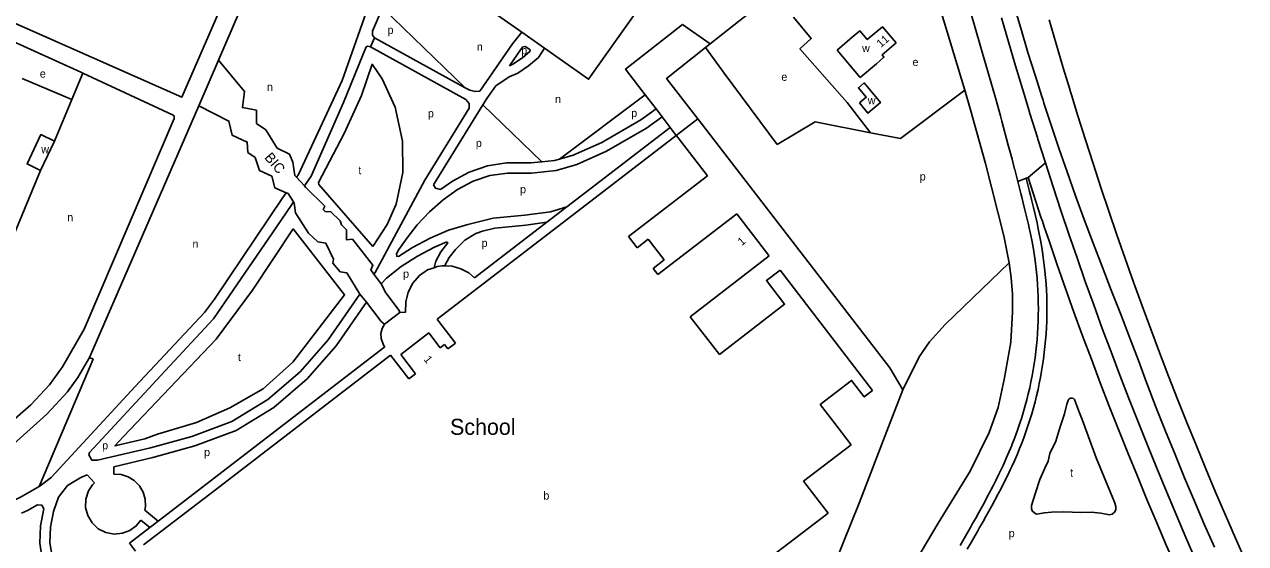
# Model space of a CAD drawing. Extents: x 155317 to 156514, y 385353 to 386894.
# Drawn here: x 155844 to 156455, y 385769 to 386029 of the extents above; entities that cross this region are included whole.
import ezdxf

# ---------------------------------------------------------------- set-up
doc = ezdxf.new("R2010")
doc.units = 0
for name, color, linetype in [('BLT_Basislijn', 7, 'Continuous'), ('BLT_Bebouwing', 7, 'Continuous'), ('BLT_Bebouwing_beschrifting', 7, 'Continuous'), ('BLT_Centroide', 7, 'Continuous'), ('BLT_Huisnummer', 7, 'Continuous'), ('BLT_Huisnummer_reeks', 7, 'Continuous'), ('BLT_Straatnaam', 7, 'Continuous'), ('BLT_Vlakafsluiter', 7, 'Continuous')]:
    doc.layers.add(name, color=color, linetype=linetype)

msp = doc.modelspace()

# ---------------------------------------------------------------- linework, layer by layer
at = {"layer": 'BLT_Basislijn'}
for p, q in [((155973.89, 386086.05), (155941.31, 386010.86)), ((156018.39, 386025.39), (156023.37, 386037.09)), ((156023.37, 386037.09), (156064.66, 385997.16)), ((156173.26, 386028.79), (156187.01, 386019.05)), ((156003.79, 385989.7), (156015.08, 386017.51)), ((156017.27, 386017.58), (156064.88, 385991.33)), ((156019.37, 386022.13), (156064.66, 385997.16)), ((156187.01, 386019.05), (156184.67, 386017.19)), ((156194.08, 386004.44), (156184.67, 386017.19)), ((155941.31, 386010.86), (155931.48, 385988.18)), ((155873.59, 386004.4), (155868.11, 385991.31)), ((156220.55, 385968.74), (156194.08, 386004.44)), ((155843.34, 386001.85), (155868.11, 385991.31)), ((156064.66, 385997.16), (156066.95, 385995.9)), ((156111.68, 385961.46), (156154.54, 385993.63)), ((156154.54, 385993.63), (156159.99, 385986.54)), ((156282.13, 385971.86), (156314.22, 385995.98)), ((155868.11, 385991.31), (155859.4, 385970.5)), ((155931.48, 385988.18), (155876.96, 385862.37)), ((156073.5, 385988.61), (156048.76, 385948.55)), ((156073.5, 385988.61), (156102.99, 385960.1)), ((156159.99, 385986.54), (156163.04, 385982.57)), ((156255.52, 385989.78), (156267.23, 385974.68)), ((156163.04, 385982.57), (156167.08, 385977.32)), ((156180.81, 385981.6), (156170.13, 385973.36)), ((156239.46, 385980.12), (156220.55, 385968.74)), ((156267.23, 385974.68), (156239.46, 385980.12)), ((156167.08, 385977.32), (156115.43, 385937.61)), ((156167.08, 385977.32), (156170.13, 385973.36)), ((156267.23, 385974.68), (156282.13, 385971.86)), ((155984.34, 385948.05), (155980.42, 385952.4)), ((155973.58, 385942.24), (155975.22, 385944.67)), ((155978.84, 385940.06), (155977.67, 385938.36)), ((156115.43, 385937.61), (156105.41, 385929.9)), ((156105.41, 385929.9), (156069.26, 385902.1)), ((156031.43, 385916.29), (156030.27, 385914.14)), ((156022.58, 385899.2), (156018.95, 385903.92)), ((156012.02, 385893.97), (156015.31, 385889.95)), ((156031.93, 385884.79), (156024.38, 385879.01)), ((156024.41, 385867.64), (155911.16, 385780.55)), ((155914.68, 385855.74), (155876.89, 385814.79)), ((155861.89, 385840.81), (155855.6, 385834)), ((155855.6, 385834), (155824.79, 385806.32)), ((155879.36, 385799.78), (155875.78, 385803.77)), ((155889.02, 385807.76), (155889.07, 385804.08)), ((155904.52, 385785.98), (155911.16, 385780.55)), ((155902.59, 385781.1), (155907.09, 385777.42)), ((155911.16, 385780.55), (155907.09, 385777.42)), ((155907.09, 385777.42), (155896.92, 385769.6)), ((155896.92, 385769.6), (155899.98, 385765.62))]:
    msp.add_line(p, q, dxfattribs=at)
for points in [[(156004.97, 386182.89), (155998.89, 386166.67), (155923.01, 385992.36), (155820.9, 386037.51)], [(156314.22, 385995.98), (156304.95, 386026.73), (156294.45, 386061.41)], [(156215.7, 386041.67), (156202.11, 386030.96), (156187.01, 386019.05)], [(155980.42, 385952.4), (155981.11, 385953.42), (156003.09, 386000.75), (156017.22, 386040.43)], [(156315.56, 386040.22), (156319.05, 386028.17), (156322.58, 386016.14), (156326.11, 386004.1), (156329.55, 385992.04), (156332.06, 385983.05), (156332.76, 385980.47)], [(156338.97, 386037.95), (156342.22, 386026.86), (156345.83, 386014.84), (156349.54, 386002.85), (156352.74, 385992.79), (156352.76, 385992.71), (156353.35, 385990.88), (156353.8, 385989.51), (156357.28, 385978.91), (156361.31, 385966.96), (156365.44, 385955.05), (156369.66, 385943.17), (156373.99, 385931.33), (156378.41, 385919.53), (156382.93, 385907.77), (156387.48, 385896.02), (156392.03, 385884.28), (156396.58, 385872.54), (156401.12, 385860.8), (156404.98, 385849.88), (156405.34, 385848.94), (156409.93, 385837.21), (156414.59, 385825.52), (156419.32, 385813.85), (156424.12, 385802.21), (156429, 385790.61), (156433.95, 385779.03), (156438.97, 385767.49)], [(156173.26, 386028.79), (156144.77, 386006.45), (156154.54, 385993.63)], [(156255.52, 385989.78), (156231.88, 386016.58), (156237.51, 386021.7), (156228.62, 386032.5)], [(156332.54, 386032.1), (156336.06, 386020.11), (156339.61, 386008.13), (156343.2, 385996.16), (156345.9, 385987.26), (156346.83, 385984.2), (156350.53, 385972.26), (156350.77, 385971.48), (156354.54, 385959.56)], [(156454.56, 385760.66), (156449.5, 385772.11), (156444.51, 385783.59), (156439.59, 385795.1), (156434.74, 385806.64), (156429.96, 385818.21), (156425.26, 385829.81), (156420.63, 385841.44), (156416.07, 385853.09), (156411.58, 385864.78), (156407.17, 385876.49), (156402.83, 385888.23), (156398.57, 385900), (156394.37, 385911.8), (156390.25, 385923.62), (156386.21, 385935.46), (156382.24, 385947.34), (156378.34, 385959.23), (156374.52, 385971.15), (156370.78, 385983.09), (156367.52, 385993.68), (156367.1, 385995.06), (156366.55, 385996.89), (156366.53, 385996.97), (156363.49, 386007.03), (156359.91, 386019.02), (156356.36, 386031.02)], [(156018.39, 386025.39), (156018.39, 386023.48), (156019.37, 386022.13)], [(156092.94, 386024.92), (156088.32, 386019.14), (156071.88, 385995.4), (156069.55, 385995.19), (156066.95, 385995.9)], [(155835.04, 386021.99), (155872.5, 386004.9), (155873.59, 386004.4)], [(156015.08, 386017.51), (156016.06, 386017.87), (156017.27, 386017.58)], [(156079.87, 385998.15), (156086.66, 386002.62), (156090.92, 386004.44), (156096.24, 386008.07), (156101.21, 386012.32), (156104.28, 386016.92)], [(156086.76, 386008.1), (156088.51, 386008.85), (156093.2, 386012.04), (156097.16, 386015.44), (156096.94, 386016.34), (156094.62, 386017.8), (156093.47, 386017.58)], [(156093.47, 386017.58), (156092.33, 386016.15), (156086.76, 386008.1)], [(156180.81, 385981.6), (156165.29, 386001.85), (156184.67, 386017.19)], [(155980.42, 385952.4), (155979.58, 385953.33), (155978.47, 385960.03), (155976.88, 385963.96), (155970.69, 385967), (155965.05, 385976.04), (155960.31, 385979.29), (155960.31, 385985.94), (155953.35, 385987.2), (155954.43, 385995.3), (155941.31, 386010.86)], [(155873.59, 386004.4), (155918.45, 385983.68), (155919.24, 385983.05), (155919.21, 385981.83), (155874.18, 385876.49), (155863.43, 385857.74), (155856.87, 385848.64), (155847.59, 385838.61), (155780.03, 385779.57)], [(156079.87, 385998.15), (156075.41, 385991.71), (156073.5, 385988.61)], [(156336.5, 385909.66), (156333.83, 385923.1), (156324.55, 385959.29), (156317.14, 385986.15), (156314.22, 385995.98)], [(155931.48, 385988.18), (155946.55, 385980.5), (155948.24, 385973.41), (155955.77, 385969.98), (155956.09, 385964.8), (155959.69, 385962.26), (155961.9, 385955.8), (155967.94, 385952.96), (155969.49, 385947.2), (155975.22, 385944.67)], [(156003.79, 385989.7), (155987.67, 385952.88), (155984.34, 385948.05)], [(156064.88, 385991.33), (156066.55, 385989.21), (156066.55, 385986.88), (156044.43, 385951.04)], [(156111.68, 385961.46), (156118.62, 385963.5), (156132.96, 385969.86), (156152.44, 385981.1), (156159.99, 385986.54)], [(156053.57, 385941.09), (156060.85, 385946.25), (156068.66, 385950.43), (156076.98, 385953.24), (156085.7, 385954.54), (156097.75, 385954.54), (156110.16, 385955.8), (156120.35, 385958.8), (156135.23, 385965.4), (156155.15, 385976.9), (156163.04, 385982.57)], [(156180.81, 385981.6), (156276.75, 385857.1), (156283.36, 385846.18)], [(156340.74, 385950.27), (156339.19, 385956.31), (156339.16, 385956.42), (156337.86, 385961.44), (156336.02, 385968.41), (156332.76, 385980.47)], [(156102.99, 385960.1), (156109.19, 385960.73), (156111.68, 385961.46)], [(155852.48, 385955.87), (155796.76, 385821.76), (155795.67, 385821.81), (155754.19, 385839.25)], [(156052.33, 385946.34), (156058.22, 385950.51), (156066.66, 385955.04), (156075.81, 385958.12), (156085.33, 385959.54), (156097.5, 385959.54), (156102.99, 385960.1)], [(156354.54, 385959.56), (156358.38, 385947.67), (156362.3, 385935.8), (156366.29, 385923.96), (156370.36, 385912.14), (156374.49, 385900.35), (156378.7, 385888.58), (156382.98, 385876.84), (156387.34, 385865.13), (156391.76, 385853.44), (156396.26, 385841.78), (156400.83, 385830.15), (156405.48, 385818.55), (156410.19, 385806.97), (156414.97, 385795.43), (156419.83, 385783.91), (156424.76, 385772.43), (156429.75, 385760.97), (156434.82, 385749.55), (156439.96, 385738.16), (156445.17, 385726.8), (156450.45, 385715.47)], [(156044.43, 385951.04), (156019.63, 385904.89), (156018.95, 385903.92)], [(156349.22, 385912.13), (156349.11, 385912.94), (156348.54, 385916.56), (156347.9, 385920.16), (156347.09, 385924.19), (156346.29, 385927.78), (156346.19, 385928.2), (156345.23, 385932.2), (156344.25, 385936.21), (156344.1, 385936.84), (156343.26, 385940.22), (156342.72, 385942.4), (156342.26, 385944.23), (156340.74, 385950.27)], [(156344.92, 385951.93), (156345.87, 385952.23)], [(156353.28, 385913.78), (156352.74, 385917.25), (156352.11, 385920.93), (156351.33, 385925.03), (156350.99, 385926.66), (156350.35, 385929.61), (156349.56, 385933.18), (156348.62, 385937.24), (156348.47, 385937.89), (156347.64, 385941.3), (156347.09, 385943.5), (156346.62, 385945.34), (156344.92, 385951.93)], [(156345.87, 385952.23), (156348.4, 385944.41), (156352.34, 385932.48), (156353.01, 385930.51), (156353.96, 385927.66), (156356.35, 385920.58), (156358.03, 385915.71)], [(155975.22, 385944.67), (155976.15, 385944.26), (155978.84, 385940.06)], [(156018.95, 385903.92), (156017.52, 385906.07), (156018.53, 385908.45), (156008.31, 385921.43), (156005.3, 385921.16), (156005.3, 385926.18), (156002.75, 385928.69), (156002.22, 385930.59), (155997.57, 385935.14), (155994.61, 385935.3), (155993.71, 385936.3), (155994.5, 385938.05), (155985, 385947.32), (155984.34, 385948.05)], [(156048.76, 385948.55), (156049.86, 385946.89), (156052.33, 385946.34)], [(155857.74, 385802.33), (155899.8, 385847.88), (155934.43, 385884.82), (155939.42, 385891.49), (155973.58, 385942.24)], [(155977.67, 385938.36), (155968.27, 385924.71)], [(155978.84, 385940.06), (155979.16, 385939.55), (155979.82, 385934.62), (155986.31, 385924.54), (155991, 385920.15), (155995, 385919.42), (155998.77, 385911.42), (155998.44, 385909.4), (156002.24, 385905.21), (156005.46, 385904.59), (156012.02, 385893.97)], [(156030.27, 385914.14), (156030.44, 385912.92), (156031.35, 385912.89), (156038.32, 385917.24), (156047.11, 385921.93), (156056.28, 385925.99), (156065.87, 385928.86), (156078.67, 385931.94), (156094.42, 385933.4), (156107.26, 385935.21), (156115.43, 385937.61)], [(156031.43, 385916.29), (156035.68, 385922.13), (156040.58, 385928.72), (156046.83, 385935.14), (156053.57, 385941.09)], [(155904.57, 385821.72), (155889.6, 385818.17), (155893.83, 385822.92), (155940.2, 385871.53), (155958.32, 385896), (155978.69, 385926.61), (156004.4, 385893.66), (155978.46, 385860.05), (155963.61, 385846.6), (155946.96, 385837.15), (155930.33, 385829.81), (155910.83, 385824.07), (155904.57, 385821.72)], [(156073.35, 385925.52), (156069.97, 385924.32), (156064.46, 385920.91), (156059.74, 385916.31), (156056.61, 385912.34), (156054.67, 385908.64), (156054.51, 385908.1)], [(156073.35, 385925.52), (156079.49, 385927), (156095, 385928.44), (156105.41, 385929.9)], [(155914.68, 385855.74), (155938.83, 385881.7), (155968.27, 385924.71)], [(156022.58, 385899.2), (156025.26, 385901.97), (156032.7, 385907.85), (156040.82, 385912.9), (156049.3, 385917.43), (156055.54, 385920.19)], [(156055.54, 385920.19), (156056.04, 385919.68), (156056.02, 385919.67), (156052.39, 385915.07), (156050.01, 385910.52), (156049.05, 385907.21)], [(156315.51, 385766.51), (156317.45, 385769.94), (156319.4, 385773.38), (156320.54, 385775.38), (156321.67, 385777.38), (156323.21, 385780.1), (156324.75, 385782.82), (156326.27, 385785.55), (156327.78, 385788.29), (156329.28, 385791.04), (156330.75, 385793.8), (156331.13, 385794.51), (156332.21, 385796.57), (156333.63, 385799.35), (156335.03, 385802.15), (156336.4, 385804.97), (156337.18, 385806.61), (156337.74, 385807.8), (156339.03, 385810.65), (156340.37, 385813.72), (156341.66, 385816.81), (156342.73, 385819.52), (156343.77, 385822.25), (156344.83, 385825.19), (156345.84, 385828.16), (156346.8, 385831.14), (156347.71, 385834.14), (156348.57, 385837.15), (156349.38, 385840.17), (156350.14, 385843.21), (156350.85, 385846.27), (156351.5, 385849.33), (156352.11, 385852.4), (156352.66, 385855.49), (156353.16, 385858.58), (156353.61, 385861.68), (156354, 385864.79), (156354.34, 385867.9), (156354.63, 385871.02), (156354.87, 385874.1), (156354.87, 385874.14), (156355.05, 385877.27), (156355.18, 385880.4), (156355.26, 385883.53), (156355.29, 385886.66), (156355.26, 385889.8), (156355.18, 385892.93), (156355.04, 385896.06), (156354.86, 385899.19), (156354.62, 385902.31), (156354.33, 385905.43), (156353.98, 385908.54), (156353.82, 385909.86), (156353.31, 385913.56), (156353.28, 385913.78)], [(156358.03, 385915.71), (156360.44, 385908.7), (156364.6, 385896.84), (156368.83, 385885.02), (156373.13, 385873.22), (156377.51, 385861.44), (156381.96, 385849.69), (156386.48, 385837.97), (156391.07, 385826.28), (156395.74, 385814.62), (156400.48, 385802.98), (156405.29, 385791.38), (156410.17, 385779.8), (156415.12, 385768.26), (156420.14, 385756.75), (156425.24, 385745.26), (156426.65, 385742.14), (156427.88, 385739.4), (156430.4, 385733.81), (156432.92, 385728.33), (156432.01, 385727.91)], [(156049.05, 385907.21), (156045.87, 385906.08), (156041.75, 385903.24), (156038.4, 385899.52), (156036.14, 385895.06), (156035.05, 385890.18), (156034.89, 385885.01), (156031.93, 385884.79)], [(156054.51, 385908.1), (156053.08, 385908.13), (156050.58, 385907.76), (156049.05, 385907.21)], [(156069.26, 385902.1), (156066.43, 385904.63), (156062.46, 385906.71), (156058.18, 385908.01), (156054.51, 385908.1)], [(156336.5, 385909.66), (156304.51, 385878.79), (156296.62, 385870.1), (156291.54, 385862.6), (156283.36, 385846.18)], [(156312.02, 385768.46), (156313.97, 385771.92), (156315.92, 385775.36), (156315.97, 385775.44), (156317.05, 385777.36), (156318.17, 385779.36), (156319.7, 385782.08), (156321.21, 385784.8), (156322.71, 385787.53), (156324.2, 385790.25), (156325.67, 385792.99), (156327.11, 385795.72), (156327.48, 385796.43), (156328.54, 385798.47), (156329.93, 385801.23), (156331.3, 385803.99), (156332.63, 385806.77), (156333.39, 385808.39), (156333.93, 385809.56), (156335.18, 385812.36), (156336.48, 385815.38), (156337.72, 385818.41), (156337.84, 385818.7), (156338.77, 385821.06), (156339.78, 385823.72), (156340.82, 385826.6), (156341.81, 385829.5), (156342.75, 385832.41), (156343.64, 385835.34), (156344.48, 385838.28), (156345.27, 385841.24), (156346.01, 385844.21), (156346.7, 385847.19), (156347.34, 385850.18), (156347.93, 385853.19), (156348.47, 385856.2), (156348.96, 385859.22), (156349.39, 385862.25), (156349.78, 385865.29), (156350.11, 385868.33), (156350.4, 385871.38), (156350.62, 385874.39), (156350.63, 385874.43), (156350.81, 385877.48), (156350.93, 385880.54), (156351.01, 385883.6), (156351.04, 385886.66), (156351.01, 385889.72), (156350.93, 385892.78), (156350.8, 385895.84), (156350.62, 385898.9), (156350.38, 385901.95), (156350.1, 385905), (156349.76, 385908.04), (156349.6, 385909.33), (156349.22, 385912.13)], [(156336.5, 385909.66), (156337.41, 385902.14), (156338.02, 385894.05), (156338.03, 385885.19), (156337.26, 385870.01), (156334.02, 385851.29), (156330.89, 385837.33)], [(156022.58, 385899.2), (156025.01, 385894.68), (156031.64, 385885.9), (156031.93, 385884.79)], [(156012.02, 385893.97), (155996.16, 385871.2), (155982.14, 385855.18), (155966.04, 385841.34), (155947.99, 385830.31), (155928.07, 385822.91), (155907.38, 385817.24), (155880.9, 385810.97), (155878.11, 385810.97), (155876.66, 385813.7), (155876.89, 385814.79)], [(156015.31, 385889.95), (156000.1, 385868.11), (155985.67, 385851.62), (155969, 385837.29), (155950.18, 385825.79), (155929.6, 385818.14), (155908.62, 385812.4), (155889.02, 385807.76)], [(156024.38, 385879.01), (156022.69, 385880.41), (156015.31, 385889.95)], [(156024.38, 385879.01), (156023.11, 385876.8), (156022.5, 385874.32), (156022.59, 385871.78), (156023.77, 385868.51), (156024.41, 385867.64)], [(155851.83, 385797.91), (155878.73, 385861.44), (155876.96, 385862.37)], [(155876.96, 385862.37), (155871.1, 385852.33), (155865.98, 385845.18), (155861.89, 385840.81)], [(156088.71, 385610.2), (156089.74, 385610.65), (156113.8, 385623.01), (156140.6, 385636.67), (156220.33, 385698.01), (156245.83, 385750.68), (156261.55, 385789.62), (156276.14, 385827.7), (156283.36, 385846.18)], [(156330.89, 385837.33), (156326.4, 385824.83), (156316.9, 385805.48), (156300.98, 385779.55), (156289.84, 385760.69), (156281.59, 385743.67), (156277.8, 385734.53), (156274.32, 385723.05), (156272.38, 385712.55), (156271.52, 385699.8), (156271.86, 385688.21), (156273.57, 385677.43), (156277.85, 385661.87), (156287.65, 385639.05), (156308.31, 385595.31), (156323.47, 385561.74)], [(155875.78, 385803.77), (155872.57, 385802.32), (155866, 385798.42), (155861.49, 385792.58), (155858.91, 385785.36), (155857.46, 385777.61), (155857.1, 385769.8), (155858.38, 385762.07), (155860.65, 385754.48), (155863.95, 385747.27), (155868.14, 385740.45), (155872.87, 385734.06), (155881.78, 385725.32), (155889.89, 385719.61), (155893.72, 385717.48)], [(155889.07, 385804.08), (155892.7, 385803.81), (155896.19, 385802.75), (155899.29, 385800.84), (155901.87, 385798.27), (155903.68, 385795.06), (155904.72, 385791.52), (155904.92, 385787.85), (155904.52, 385785.98)], [(155782.94, 385755.78), (155802.35, 385772.56), (155807.38, 385776.47), (155813.91, 385780.15), (155829.04, 385786.12), (155842.51, 385792.6), (155851.83, 385797.91)], [(155851.83, 385797.91), (155852.24, 385798.14), (155857.74, 385802.33)], [(155902.59, 385781.1), (155900.29, 385778.14), (155897.09, 385775.93), (155893.46, 385774.54), (155889.24, 385774.11), (155885.07, 385774.87), (155881.24, 385776.7), (155878.17, 385779.64), (155876.03, 385783.3), (155874.89, 385787.38), (155875.06, 385791.62), (155876.4, 385795.65), (155878.39, 385798.75), (155879.36, 385799.78)], [(155850.86, 385788.73), (155845.99, 385785.96), (155842.98, 385784.51)], [(155850.86, 385788.73), (155853.16, 385788.51), (155854.07, 385786.67), (155852.48, 385778.19), (155852.08, 385769.5), (155853.5, 385760.94), (155855.96, 385752.71), (155859.53, 385744.91), (155863.99, 385737.65), (155869.09, 385730.77), (155878.57, 385721.46), (155887.23, 385715.37), (155890.94, 385713.31)]]:
    msp.add_lwpolyline(points, dxfattribs=at)
for points in [[(156018.56, 385917.78), (155991.49, 385948.79), (155991.34, 385949.73), (156004.23, 385974.24), (156012.86, 385993.3), (156018.22, 386008.91), (156023.13, 386001.65), (156029.58, 385987.51), (156033.34, 385970.38), (156033.41, 385954.87), (156030.21, 385938.97), (156025.62, 385928.76)], [(156372.9, 385831.37), (156379.91, 385812.21), (156389.05, 385790.06), (156389.69, 385787.84), (156389.67, 385786.17), (156389.03, 385785.09), (156387.89, 385784.06), (156386.56, 385783.72), (156382.28, 385784.47), (156377.42, 385785.01), (156372.22, 385784.93), (156363.55, 385785.29), (156357.51, 385785.09), (156354.08, 385784.73), (156352.06, 385784.3), (156350.02, 385784.12), (156349.18, 385784.55), (156348, 385785.64), (156347.59, 385786.89), (156347.61, 385788.36), (156349.57, 385794.68), (156351.68, 385801.43), (156354.21, 385807.06), (156355.87, 385810.58), (156356.73, 385814.41), (156359.73, 385820.59), (156361.71, 385827.12), (156364.14, 385834.11), (156365.32, 385839.08), (156365.86, 385840.81), (156366.22, 385841.47), (156366.78, 385841.86), (156367.33, 385842.02), (156367.89, 385841.99), (156368.61, 385841.8), (156369.04, 385841.4), (156369.54, 385839.97), (156371.23, 385835.47)]]:
    msp.add_lwpolyline(points, close=True, dxfattribs=at)
at = {"layer": 'BLT_Bebouwing'}
for p, q in [((156092.94, 386024.92), (156104.28, 386016.92)), ((155859.4, 385970.5), (155852.48, 385955.87)), ((156170.13, 385973.36), (156131.77, 385943.86)), ((156171.12, 385972.07), (156170.13, 385973.36)), ((156185.72, 385953.09), (156171.12, 385972.07)), ((156146.27, 385922.75), (156185.72, 385953.09)), ((156131.77, 385943.86), (156050.59, 385881.44)), ((156200.3, 385934.13), (156160.86, 385903.79)), ((156216.36, 385913.25), (156200.3, 385934.13)), ((156150.53, 385917.22), (156146.27, 385922.75)), ((156156.1, 385921.51), (156150.53, 385917.22)), ((156164.09, 385911.12), (156156.1, 385921.51)), ((156177.04, 385882.73), (156216.48, 385913.09)), ((156216.48, 385913.09), (156216.36, 385913.25)), ((156158.52, 385906.84), (156164.09, 385911.12)), ((156160.86, 385903.79), (156158.52, 385906.84)), ((156268.2, 385845.9), (156221.96, 385905.97)), ((156191.62, 385863.79), (156177.04, 385882.73)), ((156050.59, 385881.44), (156051.46, 385880.31)), ((156051.46, 385880.31), (156059.72, 385869.51)), ((156046.48, 385874.61), (156032.47, 385863.87)), ((156052.18, 385867.17), (156046.48, 385874.61)), ((156032.47, 385863.87), (156039.84, 385854.25)), ((156054.37, 385868.86), (156052.18, 385867.17)), ((156056.04, 385866.68), (156054.37, 385868.86)), ((156059.72, 385869.51), (156056.04, 385866.68)), ((156027.34, 385863.59), (155939.8, 385796.26)), ((156036.49, 385851.68), (156027.34, 385863.59)), ((156039.84, 385854.25), (156036.49, 385851.68)), ((156257.53, 385818.76), (156248.38, 385830.65)), ((156233.75, 385800.48), (156257.53, 385818.76)), ((156245.95, 385784.61), (156233.75, 385800.48)), ((155939.8, 385796.26), (155903.94, 385768.67)), ((156210.26, 385757.19), (156245.95, 385784.61))]:
    msp.add_line(p, q, dxfattribs=at)
for points in [[(156161.54, 386051.34), (156157.51, 386054.17), (156160, 386057.7), (156099.96, 386100.04), (156097.49, 386096.49), (156093.46, 386099.39), (156058.17, 386049.45), (156092.94, 386024.92)], [(156104.28, 386016.92), (156126.3, 386001.39), (156154.84, 386041.84)], [(156250.44, 386015.94), (156258.02, 386022.35), (156261.84, 386025.58), (156265.53, 386021.21), (156273.12, 386027.63), (156279.99, 386019.51)], [(156279.99, 386019.51), (156272.91, 386013.52), (156273.88, 386012.37), (156270.07, 386009.14), (156261.98, 386002.3)], [(156261.98, 386002.3), (156250.44, 386015.94)], [(155852.48, 385955.87), (155845.71, 385959.07), (155852.64, 385973.7), (155859.4, 385970.5)], [(156221.96, 385905.97), (156215.17, 385900.74), (156224.26, 385888.92), (156191.62, 385863.79)], [(156248.38, 385830.65), (156242.08, 385838.84), (156257.68, 385850.85), (156263.99, 385842.66), (156268.2, 385845.9)]]:
    msp.add_lwpolyline(points, dxfattribs=at)
msp.add_lwpolyline([(156261.6, 385989.56), (156265.04, 385992.4), (156261.14, 385997.12), (156264.05, 385999.53), (156272.14, 385989.72), (156265.79, 385984.48)], close=True, dxfattribs=at)
at = {"layer": 'BLT_Vlakafsluiter'}
for p, q in [((156017.27, 386017.58), (156019.37, 386022.13)), ((156345.87, 385952.23), (156354.54, 385959.56)), ((156340.74, 385950.27), (156344.92, 385951.93))]:
    msp.add_line(p, q, dxfattribs=at)

# ---------------------------------------------------------------- texts
at = {"layer": 'BLT_Bebouwing_beschrifting'}
msp.add_text('School', height=8, dxfattribs=at).set_placement((156057.06, 385823.69))
at = {"layer": 'BLT_Centroide'}
for s, p in [('p', (156025.83, 386024.05)), ('n', (156070.46, 386015.65)), ('p', (156092.66, 386013.86)), ('w', (156262.95, 386014.97)), ('e', (156288.13, 386008.01)), ('e', (155852.1, 386002.21)), ('n', (155965.61, 385995.55)), ('e', (156222.6, 386000.61)), ('n', (156109.52, 385989.48)), ('w', (156265.79, 385988.87)), ('p', (156046, 385982.36)), ('p', (156147.61, 385982.53)), ('w', (155852.8, 385964.45)), ('p', (156069.95, 385967.52)), ('t', (156011.25, 385953.95)), ('p', (156291.76, 385950.8)), ('p', (156092.06, 385944.43)), ('n', (155865.8, 385930.41)), ('n', (155928.37, 385917.16)), ('p', (156072.81, 385917.58)), ('p', (156033.61, 385902.21)), ('t', (155951.11, 385860.54)), ('p', (155883.24, 385816.42)), ('p', (155934.17, 385813.06)), ('t', (156366.85, 385802.82)), ('b', (156103.7, 385791.35)), ('p', (156336.22, 385772.56))]:
    msp.add_text(s, height=4, dxfattribs=at).set_placement(p)
at = {"layer": 'BLT_Huisnummer'}
msp.add_text('11', height=4, rotation=40.21349, dxfattribs=at).set_placement((156272.28, 386017.01))
at = {"layer": 'BLT_Huisnummer_reeks'}
for rotation, p in [(40.21349, (156202.88, 385917.98)), (309.21349, (156043.68, 385861.28))]:
    msp.add_text('1', height=4, rotation=rotation, dxfattribs=at).set_placement(p)
at = {"layer": 'BLT_Straatnaam'}
msp.add_text('BIC', height=5, rotation=310.73524, dxfattribs=at).set_placement((155964.02, 385962.11))

doc.saveas('drawing.dxf')
